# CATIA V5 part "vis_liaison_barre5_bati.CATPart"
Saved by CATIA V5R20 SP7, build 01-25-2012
Part number: skl_vis_liaison_barre5_bati
Bounding box of the stored display mesh (mm): x -7 to 0, y 18 to 18, z 0 to 0
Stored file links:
  J:\IFMA\IAO\système avant mef\vis_liaison_barre5_bati.CATPart
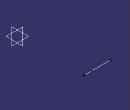
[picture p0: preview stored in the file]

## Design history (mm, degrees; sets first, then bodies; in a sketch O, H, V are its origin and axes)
Body1 (main body)
  Point1 "Point.Cprim": stored without definition
  Point2 "Point.C": stored without definition
  Line1: type PtPt, FirstPoint Point1, SecondPoint Point2
  Point3 "Point_C_vis": stored without definition
  Point4 "Point.C": stored without definition
  Line2: type PtPt, FirstPoint Point3, SecondPoint Point4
